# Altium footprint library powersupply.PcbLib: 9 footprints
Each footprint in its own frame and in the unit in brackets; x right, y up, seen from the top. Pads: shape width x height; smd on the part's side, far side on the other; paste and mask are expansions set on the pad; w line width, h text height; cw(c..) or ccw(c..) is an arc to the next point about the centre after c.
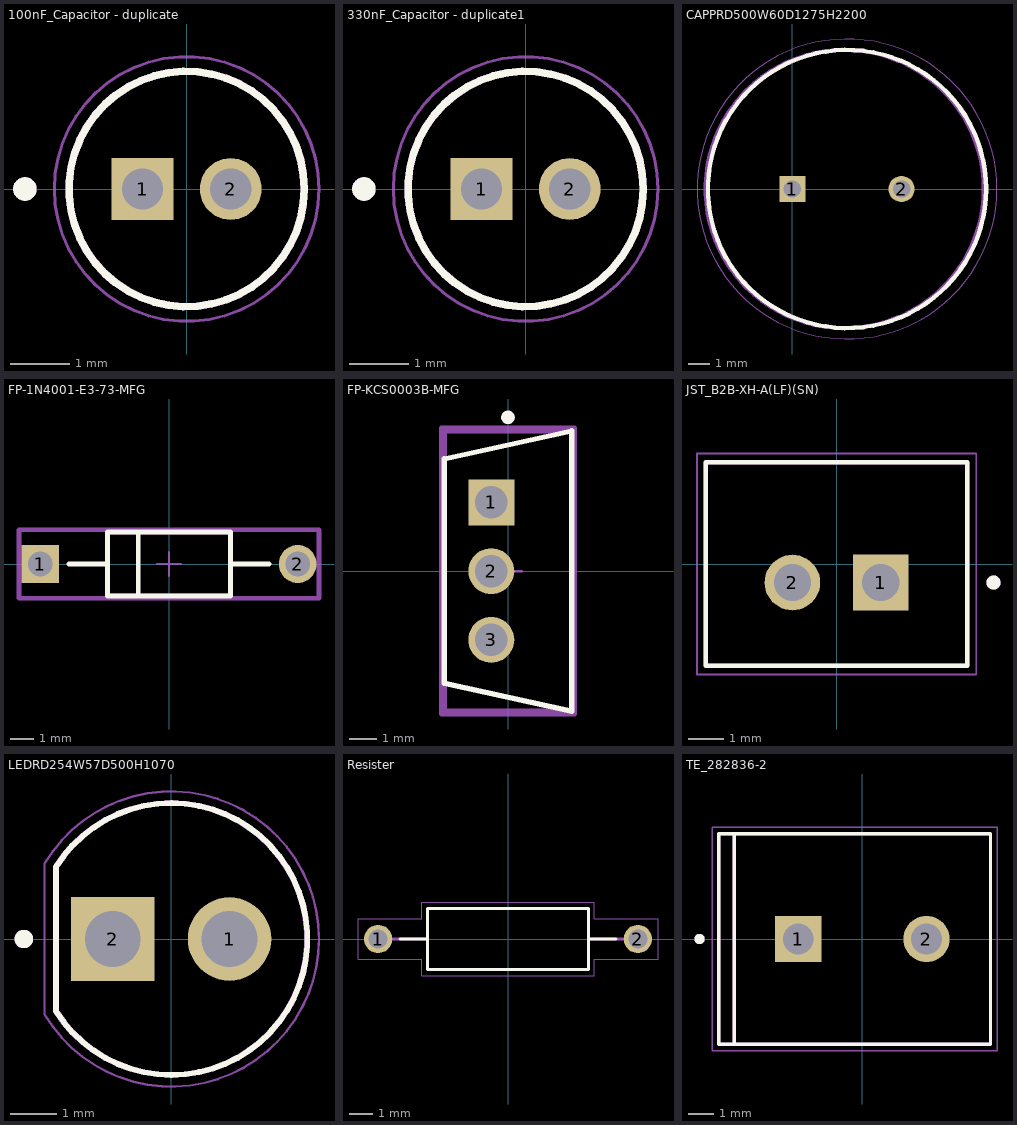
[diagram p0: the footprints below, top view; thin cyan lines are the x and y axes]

## 100nF_Capacitor - duplicate [mm]
pads (2):
  rect 1.05x1.05 hole 0.7: 1(-0.75,0)
  round 1.05 hole 0.7: 2(0.75,0)
Top Overlay:
  circle w0.2: c-2.75,0 r0.1
  circle w0.127: c0,0 r2
Top Assembly:
  circle w0.2: c-2.75,0 r0.1
  circle w0.127: c0,0 r2
  text ".Designator" at -4.953,-0.296 h1.02
Top 3D Body:
  circle w0.2: c-2.75,0 r0.1
  circle w0.127: c0,0 r2
Top Courtyard:
  circle w0.05: c0,0 r2.25
3D body "step_temp.STEP": height 7, standoff -17, extent -2,-1.999 2,1.999

## 330nF_Capacitor - duplicate1 [mm]
pads (2):
  rect 1.05x1.05 hole 0.7: 1(-0.75,0)
  round 1.05 hole 0.7: 2(0.75,0)
Top Overlay:
  circle w0.2: c-2.75,0 r0.1
  circle w0.127: c0,0 r2
Top Assembly:
  circle w0.2: c-2.75,0 r0.1
  circle w0.127: c0,0 r2
  text ".Designator" at -4.953,-0.296 h1.02
Top 3D Body:
  circle w0.2: c-2.75,0 r0.1
  circle w0.127: c0,0 r2
Top Courtyard:
  circle w0.05: c0,0 r2.25
3D body "step_temp.STEP": height 7, standoff -17, extent -2,-1.999 2,1.999

## CAPPRD500W60D1275H2200 [mm]
pads (2):
  rect 1.2x1.2 / inner round 1.2 / far side rect 1.2x1.2 hole 0.8: 1(0,0)
  round 1.2 hole 0.8: 2(5,0)
Top Overlay:
  circle w0.2: c2.5,0 r6.375
Top Assembly:
  circle w0.2: c2.4,0 r6.375
  text ".Designator" at -5.546,-0.438 h1.52
Top Courtyard:
  circle w0.1: c2.5,0 r6.375
Bottom Assembly:
  circle w0.05: c2.5,0 r6.875
3D body "MAL217255222E3.stp": height 22, standoff -10, extent -3.988,-6.497 9,6.497

## FP-1N4001-E3-73-MFG [mm]
pads (2):
  rect 1.6x1.6 hole 1.05 paste-1000 mask+0: 1(-5.438,0)
  round 1.6 hole 1.05 paste-1000 mask+0: 2(5.438,0)
Top Overlay:
  lines w0.2: -4.238,0 -2.6,0 ; -1.3,-1.28 -1.3,1.28 ; 2.6,0 4.238,0 ; -2.6,-1.35 2.6,-1.35 2.6,1.35 -2.6,1.35 -2.6,-1.35
Top Assembly:
  lines w0.2: -6.338,-1.45 6.338,-1.45 6.338,1.45 -6.338,1.45 -6.338,-1.45
  text ".Designator" at 0,0.188 h1
Top 3D Body:
  lines w0.2: -2.6,-1.35 2.6,-1.35 2.6,1.35 -2.6,1.35 -2.6,-1.35
Top Courtyard:
  lines w0.2: -6.338,-1.45 6.338,-1.45 6.338,1.45 -6.338,1.45 -6.338,-1.45
Top Component Center:
  lines w0.1: -0.5,0 0.5,0 ; 0,-0.5 0,0.5
3D body "Diode_Vishay_1N4001-E3-73_eec.STEP": height 0.25, standoff 0, extent -6.338,-1.45 6.338,1.45

## FP-KCS0003B-MFG [mm]
pads (3):
  rect 1.7x1.7 hole 1.2 paste-1000 mask+0: 1(-0.617,2.54)
  round 1.7 hole 1.2 paste-1000 mask+0: 2(-0.617,0) 3(-0.617,-2.54)
Top Overlay:
  circle w0.25: c0,5.68 r0.125
  lines w0.2: 2.35,-5.18 -2.35,-4.144 -2.35,4.144 2.35,5.18 ; 2.35,-5.13 2.35,5.13
Top Assembly:
  lines w0.2: -2.45,-5.28 -2.45,5.28 2.45,5.28 2.45,-5.28 -2.45,-5.28
  text ".Designator" at 0,-0.001 h1
Top 3D Body:
  lines w0.2: -2.35,-5.18 -2.35,5.18 2.35,5.18 2.35,-5.18 -2.35,-5.18
Top Courtyard:
  lines w0.2: -2.45,-5.28 -2.45,5.28 2.45,5.28 2.45,-5.28 -2.45,-5.28
Top Component Center:
  lines w0.1: -0.5,0 0.5,0 ; 0,-0.5 0,0.5
3D body "IC_Texas_Instruments_UA7805CKCS_eec.STEP": height 0.25, standoff 0, extent -2.45,-5.28 2.45,5.28

## JST_B2B-XH-A(LF)(SN) [mm]
height 7
pads (2):
  rect 1.575x1.575 / inner round 1.575 / far side rect 1.575x1.575 hole 1.05: 1(1.25,-0.525)
  round 1.575 hole 1.05: 2(-1.25,-0.525)
Top Overlay:
  circle w0.2: c4.44,-0.525 r0.1
  lines w0.127: -3.7,-2.875 -3.7,2.875 3.7,2.875 3.7,-2.875 -3.7,-2.875
Top 3D Body:
  circle w0.2: c4.44,-0.525 r0.1
  lines w0.127: -3.7,-2.875 -3.7,2.875 3.7,2.875 3.7,-2.875 -3.7,-2.875
Top Courtyard:
  lines w0.05: -3.95,-3.125 3.95,-3.125 3.95,3.125 -3.95,3.125 -3.95,-3.125
3D body "step_temp.STEP": height 7, standoff -3.4, extent -3.7,-2.875 3.7,2.875

## LEDRD254W57D500H1070 [mm]
height 10.7
pads (2):
  round 1.815 hole 1.21: 1(1.27,0)
  rect 1.815x1.815 / inner round 1.815 / far side rect 1.815x1.815 hole 1.21: 2(-1.27,0)
Top Overlay:
  circle w0.2: c-3.2,0 r0.1
  lines w0.127: -2.5,-1.566 ccw(c0.006,0) -2.5,1.566 -2.5,-1.566
Top Assembly:
  circle w0.2: c-3.206,0 r0.1
  lines w0.127: -2.506,-1.566 ccw(c0,0) -2.506,1.566 -2.506,-1.566
  text ".Designator" at -7.493,-0.508 h1.52
Top 3D Body:
  circle w0.2: c-3.2,0 r0.1
  lines w0.127: -2.5,-1.566 ccw(c0.006,0) -2.5,1.566 -2.5,-1.566
Top Courtyard:
  lines w0.05: -2.75,-1.64 -2.75,1.64 ; -2.743,-1.652 ccw(c0.007,0) -2.743,1.652
3D body "step_temp.STEP": height 9.1, standoff -17.8, extent -2.6,-2.95 2.95,2.95

## Resister [mm]
pads (2):
  round 1.2 hole 0.8: 1(-5.5,0) 2(5.5,0)
Top Overlay:
  lines w0.127: -4.58,0 -3.4,0 ; 4.58,0 3.4,0 ; -3.4,0 -3.4,-1.3 3.4,-1.3 3.4,0 ; -3.4,0 -3.4,1.3 3.4,1.3 3.4,0
Top Assembly:
  lines w0.127: -4.58,0 -3.4,0 ; 4.58,0 3.4,0 ; -3.4,0 -3.4,-1.3 3.4,-1.3 3.4,0 ; -3.4,0 -3.4,1.3 3.4,1.3 3.4,0
  text ".Designator" at -7.62,-0.508 h1.52
Top 3D Body:
  lines w0.127: -4.9,0 -3.4,0 ; 4.9,0 3.4,0 ; -3.4,0 -3.4,-1.3 3.4,-1.3 3.4,0 ; -3.4,0 -3.4,1.3 3.4,1.3 3.4,0
Top Courtyard:
  lines w0.05: -6.35,-0.85 -6.35,0.85 -3.65,0.85 -3.65,1.55 3.65,1.55 3.65,0.85 6.35,0.85 6.35,-0.85 3.65,-0.85 3.65,-1.55 -3.65,-1.55 -3.65,-0.85 -6.35,-0.85
3D body "step_temp.STEP": height 2.6, standoff -25.53, extent -5.775,-1.3 5.775,1.3

## TE_282836-2 [mm]
pads (2):
  rect 1.8x1.8 / inner round 1.8 / far side rect 1.8x1.8 hole 1.2: 1(-2.5,0)
  round 1.8 hole 1.2: 2(2.5,0)
Top Overlay:
  circle w0.2: c-6.35,0 r0.1
  lines w0.127: -5,-4.1 5,-4.1 5,4.1 -5,4.1 ; -5,-4.1 -5.6,-4.1 -5.6,4.1 -5,4.1 ; -5,-4.1 -5,4.1
Top Assembly:
  circle w0.2: c-6.35,0 r0.1
  lines w0.127: -5,-4.1 5,-4.1 5,4.1 -5,4.1 ; -5,-4.1 -5.6,-4.1 -5.6,4.1 -5,4.1 ; -5,-4.1 -5,4.1
  text ".Designator" at -7.9,-1.3 h1.52
Top 3D Body:
  circle w0.2: c-6.35,0 r0.1
  lines w0.127: -5,-4.1 5,-4.1 5,4.1 -5,4.1 ; -5,-4.1 -5,4.1 ; -5,-4.1 -5.6,-4.1 -5.6,4.1 -5,4.1
Top Courtyard:
  lines w0.05: -5.85,-4.35 -5.85,4.35 5.25,4.35 5.25,-4.35 -5.85,-4.35
3D body "step_temp.STEP": height 3.5, standoff -10, extent -5,-4.1 5.6,4.1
